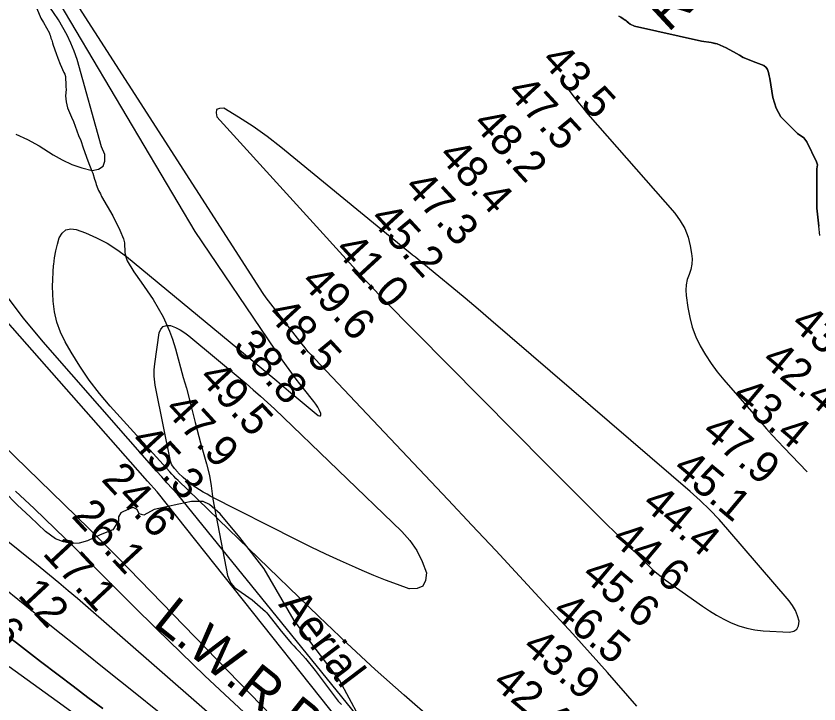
# Model space of a CAD drawing. Extents: x 3172231 to 3210228, y 940198 to 965780.
# Drawn here: x 3193133 to 3194853, y 947827 to 949300 of the extents above; entities that cross this region are included whole.
import ezdxf

# ---------------------------------------------------------------- set-up
doc = ezdxf.new("R2010")
doc.units = 0
for name, color, linetype in [('V-RIVR-EDGE', 7, 'Continuous'), ('V-RIVR-IDEN', 7, 'Continuous'), ('V-RIVR-RANG', 7, 'Continuous'), ('V-RIVR-RANG-IDEN', 7, 'Continuous'), ('V-SITE-VEGE', 7, 'Continuous'), ('V-TOPO-DPTH', 7, 'Continuous'), ('V-TOPO-MAJR', 7, 'Continuous'), ('V-TOPO-MINR', 7, 'Continuous'), ('V-TOPO-SHOR', 7, 'Continuous'), ('V-TOPO-WATR', 7, 'Continuous'), ('V-TOPO-WATR-IDEN', 7, 'Continuous')]:
    doc.layers.add(name, color=color, linetype=linetype)

msp = doc.modelspace()

# ---------------------------------------------------------------- linework, layer by layer
at = {"layer": 'V-RIVR-EDGE'}
msp.add_lwpolyline([(3193867.222, 947800.545), (3193825.683, 947877.586), (3193728.631, 948005.621), (3193664.573, 948116.623), (3193612.142, 948183.259), (3193570.103, 948233.785), (3193547.549, 948253.836), (3193533.656, 948260.391), (3193508.879, 948260.452), (3193481.481, 948254.869), (3193429.29, 948243.262), (3193407.093, 948231.58), (3193397.101, 948233.778), (3193392.778, 948243.352), (3193383.66, 948247.721), (3193374.088, 948243.833), (3193357.55, 948236.05), (3193352.748, 948227.368), (3193352.291, 948218.675), (3193347.054, 948209.995), (3193340.509, 948200.013), (3193313.097, 948189.214), (3193286.115, 948176.241), (3193268.281, 948171.069), (3193250.891, 948170.242), (3193234.818, 948174.194), (3193217.446, 948180.322), (3193196.187, 948196.458), (3193163.662, 948227.401), (3193135.905, 948252.681), (3193107.291, 948282.744)], dxfattribs=at)
at = {"layer": 'V-SITE-VEGE'}
for p, q in [((3193177.456, 949316.038), (3193186.34, 949295.861)), ((3193186.34, 949295.861), (3193192.218, 949286.268)), ((3194428.616, 949297.641), (3194424.364, 949300.086)), ((3194433.238, 949294.399), (3194428.616, 949297.641)), ((3194435.931, 949292.377), (3194433.238, 949294.399)), ((3194439.017, 949290.348), (3194435.931, 949292.377)), ((3194445.17, 949285.502), (3194439.017, 949290.348)), ((3193192.218, 949286.268), (3193204.481, 949263.333)), ((3194448.637, 949283.071), (3194445.17, 949285.502)), ((3194457.929, 949278.545), (3194448.637, 949283.071)), ((3194601.285, 949246.588), (3194457.929, 949278.545)), ((3193204.481, 949263.333), (3193204.848, 949262.143)), ((3193204.848, 949262.143), (3193206.353, 949259.153)), ((3193206.353, 949259.153), (3193207.967, 949252.419)), ((3193207.967, 949252.419), (3193209.644, 949248.243)), ((3193209.644, 949248.243), (3193211.086, 949242.695)), ((3193211.086, 949242.695), (3193212.943, 949237.923)), ((3193212.943, 949237.923), (3193218.821, 949219.864)), ((3194622.356, 949243.354), (3194601.285, 949246.588)), ((3194635.208, 949240.311), (3194622.356, 949243.354)), ((3194654.201, 949232.031), (3194635.208, 949240.311)), ((3193218.821, 949219.864), (3193222.325, 949209.737)), ((3194676.624, 949219.757), (3194654.201, 949232.031)), ((3194682.422, 949216.489), (3194676.624, 949219.757)), ((3193222.325, 949209.737), (3193227.353, 949197.408)), ((3194690.53, 949211.598), (3194682.422, 949216.489)), ((3194718.08, 949200.77), (3194690.53, 949211.598)), ((3193227.353, 949197.408), (3193235.791, 949179.289)), ((3194734.771, 949194.504), (3194718.08, 949200.77)), ((3194739.672, 949190.168), (3194734.771, 949194.504)), ((3194742.388, 949185.318), (3194739.672, 949190.168)), ((3194744.989, 949179.383), (3194742.388, 949185.318)), ((3193235.791, 949179.289), (3193237.288, 949175.904)), ((3193237.288, 949175.904), (3193238.928, 949170.351)), ((3193238.928, 949170.351), (3193239.088, 949168.772)), ((3193239.088, 949168.772), (3193240.114, 949153.779)), ((3194746.379, 949171.91), (3194744.989, 949179.383)), ((3194747.819, 949166.395), (3194746.379, 949171.91)), ((3193240.114, 949153.779), (3193239.985, 949148.268)), ((3194754.487, 949125.398), (3194747.819, 949166.395)), ((3193240.249, 949142.749), (3193238.758, 949129.586)), ((3193239.985, 949148.268), (3193240.249, 949142.749)), ((3193238.758, 949129.586), (3193240.315, 949116.252)), ((3193240.315, 949116.252), (3193243.463, 949103.482)), ((3194761.235, 949102.88), (3194754.487, 949125.398)), ((3193243.463, 949103.482), (3193252.05, 949083.385)), ((3194771.633, 949084.536), (3194761.235, 949102.88)), ((3193252.05, 949083.385), (3193256.164, 949074.032)), ((3194806.92, 949048.702), (3194771.633, 949084.536)), ((3193256.164, 949074.032), (3193267.076, 949044.039)), ((3194820.402, 949038.985), (3194806.92, 949048.702)), ((3193267.076, 949044.039), (3193272.151, 949033.676)), ((3193272.151, 949033.676), (3193276.904, 949018.007)), ((3194822.694, 949036.58), (3194820.402, 949038.985)), ((3194827.253, 949030.598), (3194822.694, 949036.58)), ((3194847.794, 948988.217), (3194827.253, 949030.598)), ((3193276.904, 949018.007), (3193287.083, 948990.195)), ((3193287.083, 948990.195), (3193295.816, 948967.931)), ((3194849.586, 948981.129), (3194847.794, 948988.217)), ((3194848.609, 948972.924), (3194849.586, 948981.129)), ((3193295.816, 948967.931), (3193297.292, 948963.762)), ((3193297.292, 948963.762), (3193301.13, 948951.066)), ((3194848.081, 948967.063), (3194848.609, 948972.924)), ((3194848.273, 948941.997), (3194848.081, 948967.063)), ((3193301.13, 948951.066), (3193302.617, 948947.289)), ((3193302.617, 948947.289), (3193303.698, 948942.931)), ((3193303.698, 948942.931), (3193304.79, 948939.163)), ((3193304.79, 948939.163), (3193308.12, 948930.025)), ((3193308.12, 948930.025), (3193310.004, 948926.435)), ((3194848.277, 948888.899), (3194848.273, 948941.997)), ((3193310.004, 948926.435), (3193313.785, 948919.652)), ((3193313.785, 948919.652), (3193316.406, 948913.878)), ((3193316.406, 948913.878), (3193328.612, 948892.766)), ((3193328.612, 948892.766), (3193340.37, 948872.136)), ((3194852.908, 948850.378), (3194848.277, 948888.899)), ((3193340.37, 948872.136), (3193355.482, 948841.863)), ((3193355.482, 948841.863), (3193363.109, 948822.775)), ((3194854.602, 948830.054), (3194852.908, 948850.378)), ((3193363.109, 948822.775), (3193365.327, 948814.339)), ((3193365.327, 948814.339), (3193366.388, 948793.45)), ((3193366.388, 948793.45), (3193368.135, 948784.527)), ((3193368.135, 948784.527), (3193371.495, 948775.651)), ((3193371.495, 948775.651), (3193385.254, 948752.361)), ((3193385.254, 948752.361), (3193401.238, 948730.12)), ((3193401.238, 948730.12), (3193426.648, 948693.356)), ((3193426.648, 948693.356), (3193448.328, 948655.855)), ((3193448.328, 948655.855), (3193461.642, 948625.424)), ((3193461.642, 948625.424), (3193468.386, 948607.938)), ((3193468.386, 948607.938), (3193474.917, 948587.292)), ((3193474.917, 948587.292), (3193490.808, 948525.721)), ((3193490.808, 948525.721), (3193498.158, 948503.033)), ((3193498.158, 948503.033), (3193507.618, 948466.503)), ((3193507.618, 948466.503), (3193516.522, 948429.713)), ((3193516.522, 948429.713), (3193527.875, 948385.851)), ((3193527.875, 948385.851), (3193541.262, 948340.842)), ((3193541.262, 948340.842), (3193547.419, 948315.942)), ((3193547.419, 948315.942), (3193550.898, 948294.131)), ((3193550.898, 948294.131), (3193554.939, 948265.465)), ((3193554.939, 948265.465), (3193586.06, 948102.129)), ((3193586.06, 948102.129), (3193590.539, 948091.696)), ((3193590.539, 948091.696), (3193594.123, 948085.131)), ((3193594.123, 948085.131), (3193601.367, 948076.515)), ((3193601.367, 948076.515), (3193638.948, 948049.829)), ((3193638.948, 948049.829), (3193667.515, 948025.132)), ((3193667.515, 948025.132), (3193669.817, 948022.517)), ((3193669.817, 948022.517), (3193671.923, 948019.908)), ((3193671.923, 948019.908), (3193672.49, 948018.911)), ((3193672.49, 948018.911), (3193701.182, 947982.786)), ((3193701.182, 947982.786), (3193722.815, 947956.281)), ((3193722.815, 947956.281), (3193728.212, 947951.228)), ((3193728.212, 947951.228), (3193732.816, 947946)), ((3193732.816, 947946), (3193738.399, 947940.552)), ((3193738.399, 947940.552), (3193747.221, 947930.496)), ((3193747.221, 947930.496), (3193752.792, 947924.459)), ((3193752.792, 947924.459), (3193774.038, 947898.355)), ((3193774.038, 947898.355), (3193823.305, 947832.6)), ((3193823.305, 947832.6), (3193830.032, 947825.549))]:
    msp.add_line(p, q, dxfattribs=at)
at = {"layer": 'V-TOPO-DPTH'}
for points in [[(3192919.413, 948561.654), (3193261.807, 948229.156), (3193290.317, 948201.226), (3193318.661, 948173.132), (3193346.758, 948144.79), (3193374.689, 948116.284), (3193705.363, 947775.832)], [(3193622.104, 947740.613), (3193264.637, 948052.465), (3193244.905, 948069.459), (3193225.03, 948086.283), (3193204.943, 948102.853), (3193184.714, 948119.253), (3193093.577, 948192.183)], [(3193622.104, 947740.613), (3193264.637, 948052.465), (3193244.905, 948069.459), (3193225.03, 948086.283), (3193204.943, 948102.853), (3193184.714, 948119.253), (3193093.577, 948192.183)], [(3193114.256, 947973.052), (3193133.764, 947957.708), (3193146.66, 947947.627), (3193159.597, 947937.6), (3193172.594, 947927.651), (3193185.633, 947917.755), (3193223.347, 947889.311), (3193255.261, 947865.216), (3193287.16, 947841.101), (3193319.034, 947816.954)], [(3193114.256, 947973.052), (3193133.764, 947957.708), (3193146.66, 947947.627), (3193159.597, 947937.6), (3193172.594, 947927.651), (3193185.633, 947917.755), (3193223.347, 947889.311), (3193255.261, 947865.216), (3193287.16, 947841.101), (3193319.034, 947816.954)]]:
    msp.add_lwpolyline(points, dxfattribs=at)
at = {"layer": 'V-TOPO-MAJR'}
msp.add_lwpolyline([(3194026.674, 947791.154), (3193964.316, 947845.715), (3193902.602, 947900.982), (3193841.85, 947957.306), (3193781.742, 948014.335), (3193480.368, 948305.256), (3193475.714, 948309.842), (3193471.123, 948314.488), (3193466.627, 948319.228), (3193462.196, 948324.028), (3193335.005, 948464.651), (3193311.787, 948492.052), (3193289.817, 948520.359), (3193269.72, 948550.024), (3193250.871, 948580.596), (3193238.226, 948602.67), (3193228.259, 948623.363), (3193220.347, 948644.659), (3193215.518, 948666.857), (3193212.744, 948689.657), (3193211.955, 948705.502), (3193211.549, 948720.843), (3193211.62, 948736.171), (3193212.406, 948751.479), (3193213.668, 948766.773), (3193213.803, 948768.054), (3193215.779, 948782.611), (3193218.313, 948797.053), (3193221.686, 948811.323), (3193225.617, 948825.478), (3193232, 948835.394), (3193239.915, 948842.175), (3193250.128, 948844.253), (3193261.873, 948843.197), (3193282.208, 948835.509), (3193305.51, 948825.353), (3193327.977, 948813.759), (3193349.194, 948800.008), (3193369.576, 948784.819), (3193641.143, 948560.712), (3193666.413, 948539.8), (3193691.645, 948518.843), (3193716.82, 948497.818), (3193741.958, 948476.747), (3193780.44, 948444.402), (3193783.075, 948443.869), (3193785.037, 948444.252), (3193785.988, 948446.01), (3193786.266, 948448.684), (3193783.036, 948455.594), (3193779.444, 948462.29), (3193775.31, 948468.667), (3193770.815, 948474.829), (3193748.711, 948502.63), (3193733.126, 948522.705), (3193717.859, 948543.013), (3193703.067, 948563.67), (3193688.593, 948584.56), (3193516.705, 948838.904), (3193152.618, 949453.266)], dxfattribs=at)
at = {"layer": 'V-TOPO-MINR'}
for points in [[(3194463.134, 947822.044), (3194399.946, 947894.07), (3194381.525, 947914.921), (3194363.008, 947935.686), (3194344.347, 947956.322), (3194325.59, 947976.872), (3194262.151, 948045.895), (3194211.483, 948100.78), (3194160.655, 948155.516), (3194109.588, 948210.029), (3194058.361, 948264.393), (3193772.965, 948565.938), (3193765.944, 948573.576), (3193759.076, 948581.345), (3193752.437, 948589.31), (3193745.95, 948597.406), (3193668.689, 948696.769), (3193662.332, 948705.821), (3193157.503, 949490.958)], [(3193132.361, 949047.169), (3193157.962, 949035.837), (3193182.711, 949022.169), (3193212.498, 949003.006), (3193232.211, 948991.879), (3193252.563, 948982.352), (3193273.875, 948975.224), (3193295.827, 948969.696), (3193309.683, 948972.386), (3193319.522, 948978.339), (3193323.337, 948989.188), (3193323.135, 949003.301), (3193316.239, 949019.847), (3193264.141, 949206.888), (3193257.773, 949224.633), (3193250.581, 949242.114), (3193242.316, 949259.14), (3193233.457, 949275.831), (3193223.708, 949292.018), (3193213.365, 949307.869), (3193145.795, 949405.528), (3193128.55, 949430.715)], [(3194299.526, 949166.179), (3194315.888, 949143.434), (3194325.999, 949129.794), (3194336.364, 949116.355), (3194347.108, 949103.217), (3194358.106, 949090.281), (3194544.184, 948877.629), (3194555.857, 948861.798), (3194565.604, 948845.05), (3194572.461, 948826.926), (3194577.391, 948807.885), (3194580.176, 948791.651), (3194581.115, 948780.123), (3194580.736, 948768.755), (3194578.38, 948757.628), (3194574.707, 948746.66), (3194570.966, 948735.684), (3194568.466, 948724.535), (3194567.83, 948713.127), (3194568.437, 948701.547), (3194571.89, 948676.232), (3194576.022, 948654.717), (3194581.642, 948633.688), (3194589.493, 948613.385), (3194598.832, 948593.568), (3194609.926, 948574.546), (3194621.824, 948556.08), (3194634.927, 948538.449), (3194648.833, 948521.375), (3194728.321, 948430.183), (3194740.483, 948416.417), (3194752.764, 948402.76), (3194765.226, 948389.268), (3194777.808, 948375.885), (3194827.341, 948323.897)], [(3193562.763, 949099.645), (3193561.441, 949093.112), (3193563.283, 949084.062), (3193883.24, 948732.663), (3193892.24, 948722.901), (3193901.321, 948713.214), (3193910.52, 948703.641), (3193919.799, 948694.143), (3194269.697, 948340.423), (3194308.71, 948301.13), (3194347.822, 948261.936), (3194387.079, 948222.888), (3194426.434, 948183.937), (3194489.195, 948122.053), (3194497.418, 948114.327), (3194505.873, 948106.877), (3194514.676, 948099.842), (3194523.711, 948093.083), (3194603.329, 948036.458), (3194618.164, 948026.523), (3194633.334, 948017.167), (3194649.005, 948008.677), (3194665.011, 948000.765), (3194681.515, 947994.279), (3194698.338, 947989.074), (3194715.639, 947985.791), (3194733.259, 947983.79), (3194789.872, 947980.583), (3194798.949, 947982.925), (3194805.75, 947987.257), (3194809.135, 947994.576), (3194810.243, 948003.885), (3194806.954, 948015.811), (3194802.524, 948027.188), (3194796.382, 948037.74), (3194789.1, 948047.742), (3194658.103, 948200.802), (3194638.927, 948222.193), (3194619.131, 948242.965), (3194598.402, 948262.808), (3194577.053, 948282.031), (3194150.39, 948648.837), (3194122.7, 948672.46), (3194094.892, 948695.94), (3194066.907, 948719.209), (3194038.802, 948742.336), (3193994.587, 948778.44), (3193988.502, 948783.41), (3193982.419, 948788.382), (3193976.337, 948793.355), (3193970.256, 948798.33), (3193700.517, 949019.087), (3193671.178, 949041.844), (3193641.111, 949063.533), (3193609.951, 949083.622), (3193578.064, 949102.645), (3193568.831, 949102.403), (3193562.763, 949099.645)], [(3193990.132, 947582.853), (3193435.21, 948281.192), (3193414.711, 948304.365), (3193394.229, 948327.554), (3192776.766, 949027.338)], [(3194075.59, 947539.997), (3193478.63, 948275.88), (3193467.378, 948288.229), (3193456.181, 948300.628), (3193445.065, 948313.1), (3193434.005, 948325.621), (3193190.945, 948602.624), (3193149.246, 948653.3), (3193109.807, 948705.57)], [(3193533.976, 948280.609), (3193525.877, 948285.591), (3193517.898, 948290.779), (3193514.822, 948292.863), (3193508.595, 948297.316), (3193502.532, 948301.969), (3193496.713, 948306.925), (3193491.057, 948312.083), (3193480.541, 948322.174), (3193479.479, 948323.267), (3193472.238, 948331.272), (3193470.792, 948332.973), (3193468.158, 948336.564), (3193465.942, 948340.424), (3193464.368, 948344.549), (3193463.822, 948346.703), (3193432.487, 948502.78), (3193431.332, 948509.287), (3193430.373, 948515.819), (3193429.708, 948522.388), (3193429.239, 948528.981), (3193429.1, 948535.584), (3193429.202, 948542.177), (3193429.666, 948548.754), (3193430.372, 948555.321), (3193439.388, 948621.923), (3193443.053, 948629.835), (3193448.16, 948635.401), (3193455.432, 948637.45), (3193464.146, 948637.153), (3193474.676, 948632.852), (3193484.805, 948627.84), (3193494.331, 948621.76), (3193503.455, 948614.968), (3193625.8, 948513.084), (3193641.352, 948499.85), (3193656.711, 948486.401), (3193671.781, 948472.628), (3193686.657, 948458.639), (3193959.48, 948196.568), (3193976.923, 948176.826), (3193991.956, 948155.652), (3194003.374, 948132.328), (3194012.382, 948107.572), (3194010.467, 948091.287), (3194004.421, 948079.414), (3193992.177, 948074.159), (3193975.802, 948073.316), (3193975.479, 948073.428), (3193950.053, 948082.544), (3193924.778, 948092.048), (3193899.73, 948102.132), (3193874.831, 948112.603), (3193860.194, 948118.959), (3193828.226, 948133.186), (3193796.437, 948147.795), (3193764.918, 948162.978), (3193733.579, 948178.542), (3193550.66, 948271.465), (3193542.258, 948275.934), (3193533.976, 948280.609)], [(3193705.363, 947775.832), (3193374.689, 948116.284), (3193346.758, 948144.79), (3193318.661, 948173.132), (3193290.317, 948201.226), (3193261.807, 948229.156), (3192919.413, 948561.654)], [(3193948.236, 947505.467), (3193590.104, 947838.236), (3193537.785, 947887.391), (3193485.833, 947936.927), (3193434.431, 947987.034), (3193383.397, 948037.522), (3193302.459, 948118.482), (3193292.139, 948128.745), (3193281.781, 948138.969), (3193271.365, 948149.133), (3193260.909, 948159.258), (3193171.635, 948245.211), (3193131.971, 948282.442)], [(3193439.71, 947808.478), (3193384.541, 947852.741), (3193329.33, 947896.949), (3193274.09, 947941.123), (3193216.54, 947987.099), (3193190.052, 948008.255), (3193163.562, 948029.409), (3193137.068, 948050.558), (3193110.571, 948071.704)], [(3193319.034, 947816.954), (3193287.16, 947841.101), (3193255.261, 947865.216), (3193223.347, 947889.311), (3193185.633, 947917.755), (3193172.594, 947927.651), (3193159.597, 947937.6), (3193146.66, 947947.627), (3193133.764, 947957.708), (3193114.256, 947973.052)], [(3193297.157, 947777.149), (3193221.339, 947832.3), (3193118.554, 947906.458)]]:
    msp.add_lwpolyline(points, dxfattribs=at)
at = {"layer": 'V-TOPO-SHOR'}
msp.add_lwpolyline([(3194424.364, 949300.088), (3194428.616, 949297.641), (3194433.238, 949294.399), (3194435.931, 949292.377), (3194439.017, 949290.348), (3194442.094, 949287.925), (3194445.17, 949285.502), (3194448.637, 949283.071), (3194457.929, 949278.545), (3194601.285, 949246.59), (3194622.356, 949243.354), (3194629.756, 949241.614), (3194635.208, 949240.311), (3194654.201, 949232.031), (3194676.624, 949219.757), (3194682.422, 949216.489), (3194690.53, 949211.598), (3194718.08, 949200.77), (3194734.771, 949194.504), (3194739.672, 949190.17), (3194742.388, 949185.318), (3194744.989, 949179.383), (3194745.689, 949175.842), (3194746.379, 949171.91), (3194747.817, 949166.395), (3194754.487, 949125.4), (3194761.237, 949102.88), (3194771.633, 949084.536), (3194806.922, 949048.7), (3194820.4, 949038.985), (3194822.694, 949036.58), (3194827.253, 949030.6), (3194847.794, 948988.217), (3194849.586, 948981.127), (3194848.609, 948972.924), (3194848.081, 948967.063), (3194848.273, 948941.997), (3194848.277, 948888.899), (3194852.908, 948850.378)], dxfattribs=at)
at = {"layer": 'V-TOPO-WATR'}
msp.add_lwpolyline([(3193622.104, 947740.613), (3193264.637, 948052.465), (3193244.905, 948069.459), (3193225.03, 948086.283), (3193204.943, 948102.853), (3193184.714, 948119.253), (3193093.577, 948192.183)], dxfattribs=at)

# ---------------------------------------------------------------- texts
at = {"layer": 'V-RIVR-IDEN'}
msp.add_text('Aerial', height=67, rotation=307.162273, dxfattribs=at).set_placement((3193693.84, 948039.655))
at = {"layer": 'V-RIVR-RANG'}
for s, rotation, p in [('43.5', 312.688326, (3194255.545, 949203.488)), ('47.5', 312.688326, (3194182.203, 949135.51)), ('48.2', 312.688326, (3194108.862, 949067.532)), ('48.4', 312.688326, (3194035.52, 948999.554)), ('47.3', 312.688326, (3193962.178, 948931.576)), ('45.2', 312.688326, (3193888.837, 948863.598)), ('41.0', 312.688326, (3193813.528, 948797.753)), ('49.6', 312.688326, (3193740.902, 948728.999)), ('48.5', 312.688326, (3193668.812, 948659.664)), ('43.6', 320.028326, (3194790.205, 948636.046)), ('38.8', 312.688326, (3193595.47, 948591.686)), ('42.4', 320.028326, (3194727.564, 948558.069)), ('49.5', 312.688326, (3193522.128, 948523.709)), ('43.4', 320.028326, (3194663.507, 948481.279)), ('47.9', 312.688326, (3193448.609, 948455.925)), ('47.9', 320.028326, (3194599.247, 948404.659)), ('45.3', 312.688326, (3193375.445, 948387.753)), ('45.1', 320.028326, (3194537.213, 948326.174)), ('24.6', 312.955556, (3193313.846, 948306.35)), ('44.4', 320.028326, (3194471.337, 948250.909)), ('26.1', 312.955556, (3193250.033, 948228.139)), ('44.6', 320.028326, (3194405.864, 948175.305)), ('17.1', 312.955556, (3193187.835, 948148.192)), ('45.6', 320.028326, (3194341.807, 948098.515)), ('12', 312.955556, (3193134.804, 948058.399)), ('46.5', 320.028326, (3194279.167, 948020.538)), ('6', 312.955556, (3193073.686, 947977.293)), ('43.9', 320.028326, (3194214.907, 947943.918)), ('42.4', 320.028326, (3194151.053, 947866.958))]:
    msp.add_text(s, height=67, rotation=rotation, dxfattribs=at).set_placement(p)
at = {"layer": 'V-RIVR-RANG-IDEN'}
msp.add_text('R-314.35', height=82.9998, rotation=42.826497, dxfattribs=at).set_placement((3194529.934, 949263.813))
at = {"layer": 'V-TOPO-WATR-IDEN'}
msp.add_text('L.W.R.P.', height=83, rotation=321.33929, dxfattribs=at).set_placement((3193423.919, 947996.278))

doc.saveas('drawing.dxf')
